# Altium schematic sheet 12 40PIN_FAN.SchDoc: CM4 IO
size 297 x 209 mm; Page Create Date: March  8, 1995; Page Number: 12; Page Size: A4; Comment: radxa_1010; Page Count: 19; RevCode: V1.10; Doc: 12 40PIN/FAN; DsnPath: D:\WMS\黄工\[RC126]CM4_IO_V1.10\[RC126]_V1.10\CM4 IO_V1.10.DSN; SchematicName: CM4 IO V1.10; PageName: 12 40PIN/FAN; PageSize: A4; TopSchematic: True
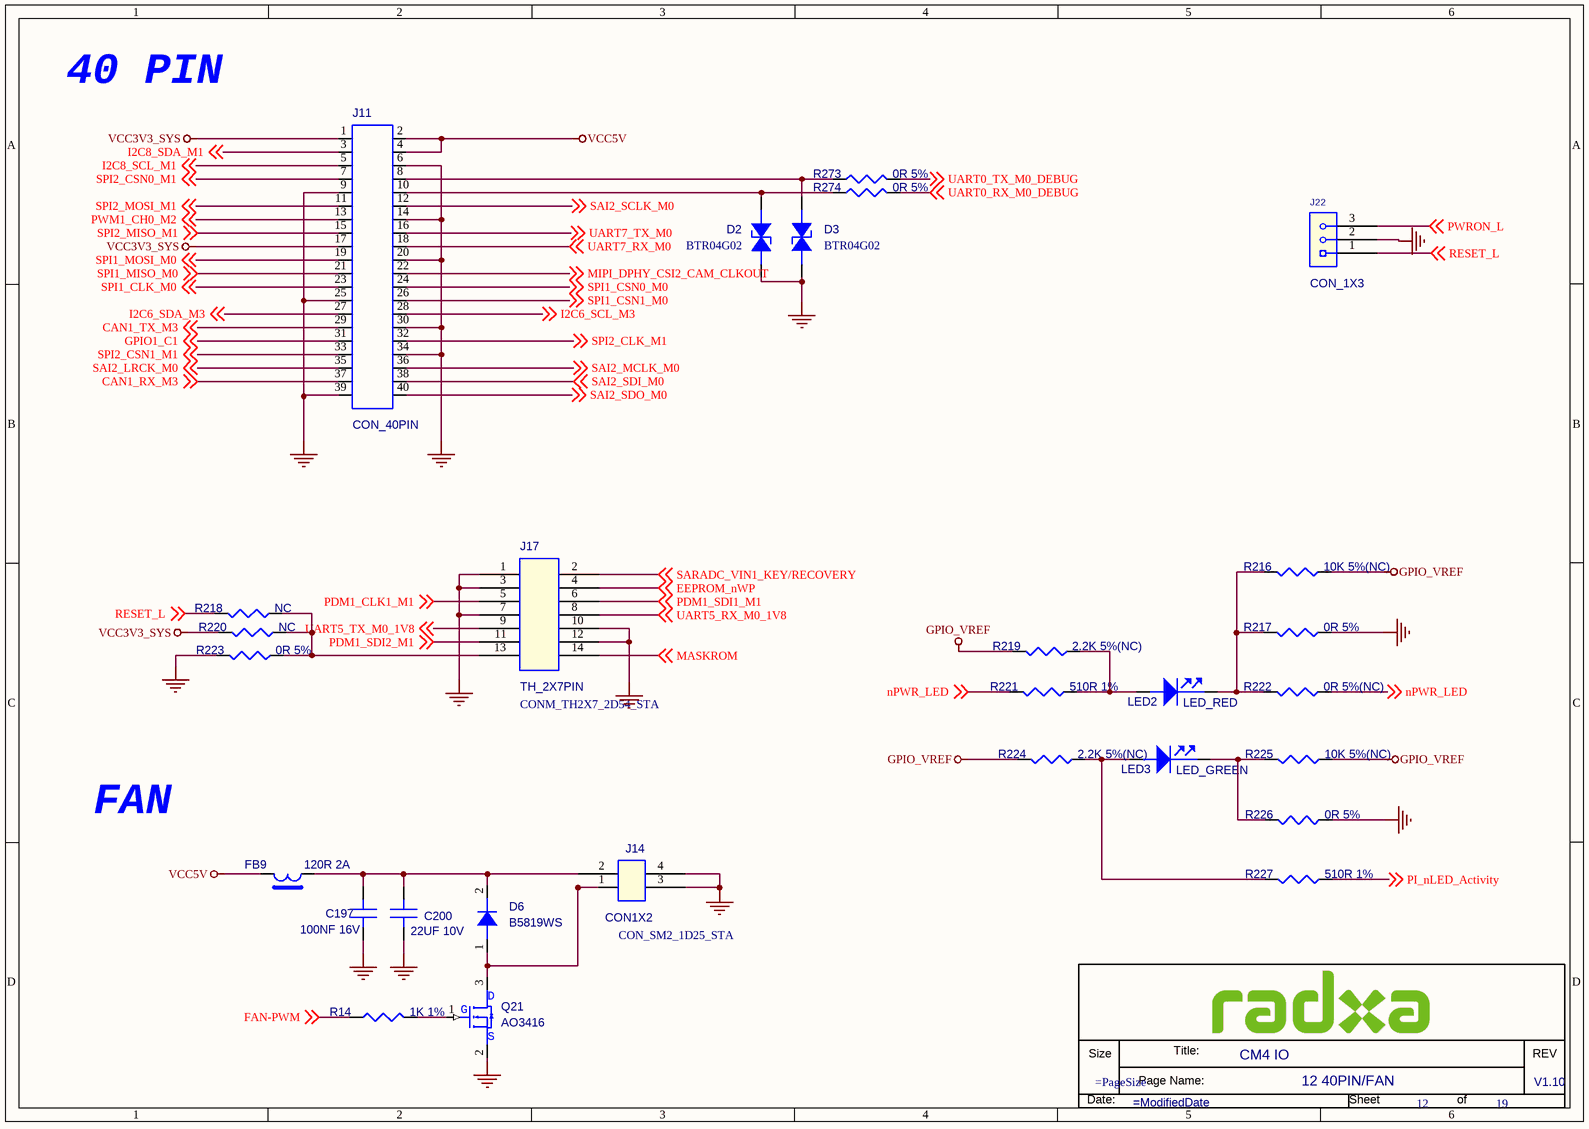
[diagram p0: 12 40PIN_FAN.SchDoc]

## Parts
*  Doc: 12 40PIN/FAN  RevCode: V1.10  Title: CM4 IO  Page Number: 12  Page Count: 19  (hidden comment: radxa_1010)  (graphical)
C197  100NF 16V  [C0201]
C200  22UF 10V  [C0603]
D2  BTR04G02  [DFN1006-2L]
D3  BTR04G02  [DFN1006-2L]
D6  B5819WS  [SOD_323]
FB9  120R 2A  [FB0402]
J11  CON_40PIN  [CON_TH20X2_2D54_STA]
J14  CON1X2  [CON_SM2_1D25_STA]
J17  TH_2X7PIN  [CONM_TH2X7_2D54_STA]
J22  CON_1X3  [CON_TH1X3_2D54_STA]
LED2  LED_RED  [LED_D0603]
LED3  LED_GREEN  [LED_D0603]
Q21  AO3416  [SOT_23]
R14  1K 1%  [R0402]
R216  10K 5%(NC)  [R0402]
R217  0R 5%  [R0402]
R218  NC  [R0402]
R219  2.2K 5%(NC)  [R0402]
R220  NC  [R0402]
R221  510R 1%  [R0402]
R222  0R 5%(NC)  [R0402]
R223  0R 5%  [R0402]
R224  2.2K 5%(NC)  [R0402]
R225  10K 5%(NC)  [R0402]
R226  0R 5%  [R0402]
R227  510R 1%  [R0402]
R273  0R 5%  [R0402]
R274  0R 5%  [R0402]

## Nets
GND: C197.2(B) C200.2(B) D2.2(CATHODE) D3.2(CATHODE) J11.6 J11.9 J11.14 J11.20 J11.25 J11.30 J11.34 J11.39 J14.3 J14.4 J17.1 J17.3 J17.7 J17.10 J17.12 J22.2 Q21.2(S) R217.2 R223.2 R226.2
GPIO_VREF: R216.2 R219.1 R224.1 R225.2
VCC3V3_SYS: J11.1 J11.17 R220.2
VCC5V: FB9.1 J11.2 J11.4
CAN1_RX_M3: J11.37 ; off-sheet CAN1_RX_M3
CAN1_TX_M3: J11.29 ; off-sheet CAN1_TX_M3
EEPROM_nWP: J17.4 ; off-sheet EEPROM_nWP
FAN-PWM: R14.1 ; off-sheet FAN-PWM
GPIO1_C1: J11.31 ; off-sheet GPIO1_C1
I2C6_SCL_M3: J11.28 ; off-sheet I2C6_SCL_M3
I2C6_SDA_M3: J11.27 ; off-sheet I2C6_SDA_M3
I2C8_SCL_M1: J11.5 ; off-sheet I2C8_SCL_M1
I2C8_SDA_M1: J11.3 ; off-sheet I2C8_SDA_M1
MASKROM: J17.14 ; off-sheet MASKROM
MIPI_DPHY_CSI2_CAM_CLKOUT: J11.22 ; off-sheet MIPI_DPHY_CSI2_CAM_CLKOUT
nPWR_LED: R221.1 R222.2 ; off-sheet nPWR_LED
PDM1_CLK1_M1: J17.5 ; off-sheet PDM1_CLK1_M1
PDM1_SDI1_M1: J17.6 ; off-sheet PDM1_SDI1_M1
PDM1_SDI2_M1: J17.11 ; off-sheet PDM1_SDI2_M1
PI_nLED_Activity: R227.2 ; off-sheet PI_nLED_Activity
PWM1_CH0_M2: J11.13 ; off-sheet PWM1_CH0_M2
PWRON_L: J22.3 ; off-sheet PWRON_L
RESET_L: J22.1 R218.2 ; off-sheet RESET_L
SAI2_LRCK_M0: J11.35 ; off-sheet SAI2_LRCK_M0
SAI2_MCLK_M0: J11.36 ; off-sheet SAI2_MCLK_M0
SAI2_SCLK_M0: J11.12 ; off-sheet SAI2_SCLK_M0
SAI2_SDI_M0: J11.38 ; off-sheet SAI2_SDI_M0
SAI2_SDO_M0: J11.40 ; off-sheet SAI2_SDO_M0
SARADC_VIN1_KEY/RECOVERY: J17.2 ; off-sheet SARADC_VIN1_KEY/RECOVERY
SPI1_CLK_M0: J11.23 ; off-sheet SPI1_CLK_M0
SPI1_CSN0_M0: J11.24 ; off-sheet SPI1_CSN0_M0
SPI1_CSN1_M0: J11.26 ; off-sheet SPI1_CSN1_M0
SPI1_MISO_M0: J11.21 ; off-sheet SPI1_MISO_M0
SPI1_MOSI_M0: J11.19 ; off-sheet SPI1_MOSI_M0
SPI2_CLK_M1: J11.32 ; off-sheet SPI2_CLK_M1
SPI2_CSN0_M1: J11.7 ; off-sheet SPI2_CSN0_M1
SPI2_CSN1_M1: J11.33 ; off-sheet SPI2_CSN1_M1
SPI2_MISO_M1: J11.15 ; off-sheet SPI2_MISO_M1
SPI2_MOSI_M1: J11.11 ; off-sheet SPI2_MOSI_M1
UART0_RX_M0_DEBUG: R274.2 ; off-sheet UART0_RX_M0_DEBUG
UART0_TX_M0_DEBUG: R273.2 ; off-sheet UART0_TX_M0_DEBUG
UART5_RX_M0_1V8: J17.8 ; off-sheet UART5_RX_M0_1V8
UART5_TX_M0_1V8: J17.9 ; off-sheet UART5_TX_M0_1V8
UART7_RX_M0: J11.18 ; off-sheet UART7_RX_M0
UART7_TX_M0: J11.16 ; off-sheet UART7_TX_M0
NetC197_1: C197.1(A) C200.1(A) D6.2(K) FB9.2 J14.2
NetD2_1: D2.1(ANODE) J11.10 R274.1
NetD3_1: D3.1(ANODE) J11.8 R273.1
NetD6_1: D6.1(A) J14.1 Q21.3(D)
NetJ17_13: J17.13 R218.1 R220.1 R223.1
NetLED2_1: LED2.1(ANODE) R219.2 R221.2
NetLED2_2: LED2.2(CATHODE) R216.1 R217.1 R222.1
NetLED3_1: LED3.1(ANODE) R224.2 R227.1
NetLED3_2: LED3.2(CATHODE) R225.1 R226.1
NetQ21_1: Q21.1(G) R14.2

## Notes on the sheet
- 40 PIN
- FAN

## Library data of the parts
C197 = C: SMD  0201  100NF  16V  X5R  ±20%  ROHS; PARTS: 1; Part Reference: C197; Part Number: A1C01.00099; OriginalSymbolOrigin: (0,30); PKG_TYPE: CAP2-100-250; LEVEL: STD; PINSWAP: (A,B)
C200 = C: SMD  0603  22UF  10V  X5R  ±20%  ROHS; PARTS: 1; Part Reference: C200; Part Number: A1C01.00015; OriginalSymbolOrigin: (0,30); PKG_TYPE: CAP2-100-250; LEVEL: STD; PINSWAP: (A,B)
D2 = ESD: SMD  编带  0402  BTR04G02  B-tron  ROHS; Part Reference: D2; Part Number: A1D02.00002; Parameter: ESD-台舟 ESD5341N-封装 esd0402; ID: DE-E0004; Preferred: 6715f349cd0bc5; Temp Coeff: -50℃ to +125℃; PCB Footprint: ESD_D0402
D3 = ESD: SMD  编带  0402  BTR04G02  B-tron  ROHS; Part Reference: D3; Part Number: A1D02.00002; Parameter: ESD-台舟 ESD5341N-封装 esd0402; ID: DE-E0004; Temp Coeff: -50℃ to +125℃; Preferred: 6715f349cd0bc5; PCB Footprint: ESD_D0402
D6 = DIODE_Dup1: SMD  编带  SOD-323  B5819WS  CJ  ROHS; Part Reference: D6; Manufacturer: 长电; Part Number: A1D02.00005; RK PN: B5819W; Priority: A; Temp Coeff: -55℃ ~ ＋150℃
FB9 = BEAD: SMD  0402  FB120R  2A  ±25%  ROHS; Part Reference: FB9; Part Number: A1L09.00004; Preferred: 6715f349cd0bc5; Temp Coeff: -55℃ to +125℃
J11 = CON_TH2X20: DIP  排针座  2*20PIN  180度  2.54mm脚距  中间朔高2.5mm  针长一端6.1mm  另一端3.0mm  彩色  PH2.54  2*20P  彩印 L=11.6/3.0  国意英  ROHS; Part Reference: J11; Part Number: A1J01.00012; OriginalSymbolOrigin: (-100,550); Preferred: 6715f349cd0bc5; Temp Coeff: -40℃ to +105℃
J14 = CON_1X2: SMD  母座  1*2PIN  90度  立贴  1.25mm脚距  9T  X9821WVS-02-9TSN  白色  星坤  ROHS; Part Reference: J14; Part Number: A1J01.00089; Temp Coeff: -25℃ to +85℃; Preferred: 6715f352cd0bcd
J17 = TH_2X7PIN: DIP  排针座  2*7PIN  180度  2.54mm脚距  中间朔高2.5mm  针长一端6.1mm  另一端3.0mm  黑色  PH2.54 2*7P L=11.6/3.0 S/T  国意英  ROHS; Part Reference: J17; Part Number: A1J02.00017; Preferred: 6715f349cd0bc5
J22 = CON_1X3: DIP  排针座  1*3PIN  180度  2.54mm脚距  中间朔高2.5mm  针长一端6.1mm  另一端3.0mm  材质LCP  黑色  PH2.54 1*3P L=11.6/3.0  国意英  ROHS; Part Reference: J22; Part Number: A1J02.00013; OriginalSymbolOrigin: (-50,50); Temp Coeff: -40°C to +85°C; Preferred: 6715f349cd0bc5
LED2 = LED: SMD  编带  0603  发红光  单色  mcd=150  IF=20mA  无色散光  EY-PB0603RC-010F  恩域光电  ROHS; Part Reference: LED2; Part Number: A1D03.00003; RK PN: LED_GREEN; Priority: A; Temp Coeff: -40℃ to +85℃; Preferred: 6715f349cd0bc5
LED3 = LED: SMD  编带  0603  发绿光  单色  mcd=150  IF=20mA  无色散光  EY-TB0603GC-010F  恩域光电  ROHS; Part Reference: LED3; Part Number: A1D03.00002; Priority: A; Temp Coeff: -40℃ to +85℃
Q21 = MOSFET_NPN: SMD  编带  SOT-23-3L  AO3416  N沟道  AOS  ROHS; Part Reference: Q21; Part Number: A1D01.00010; Temp Coeff: -55℃ to ＋150℃
R14 = R: SMD  0201  1K  1/20W  ±1%  ROHS; Part Reference: R14; Part Number: A1R01.00111; PCB Footprint: R0201; Preferred: 6715f349cd0bc5
R216 = R: SMD  0201  10K  1/20W  ±5%  ROHS; Part Reference: R216; Part Number: A1R01.00012; PCB Footprint: R0201; Temp Coeff: -55℃ to +125℃; Preferred: 6715f349cd0bc5
R217 = R: SMD  0201  0R  1/20W  ±5%  ROHS; Part Reference: R217; Part Number: A1R01.00027; PCB Footprint: R0201; Preferred: 6715f349cd0bc5; Temp Coeff: -55℃ to +125℃
R218 = R: SMD  0201  0R  1/20W  ±5%  ROHS; Part Reference: R218; Part Number: A1R01.00027; PCB Footprint: R0201; Preferred: 6715f349cd0bc5; Temp Coeff: -55℃ to +125℃
R219 = R: SMD  0201  2.2K  1/20W  ±5%  ROHS; Part Reference: R219; Part Number: A1R01.00016; PCB Footprint: R0201; Preferred: 6715f349cd0bc5; Temp Coeff: -55℃ to +125℃
R220 = R: SMD  0201  10K  1/20W  ±5%  ROHS; Part Reference: R220; Part Number: A1R01.00012; PCB Footprint: R0201; Preferred: 6715f349cd0bc5; Temp Coeff: -55℃ to +125℃
R221 = R: SMD  0201  2.2K  1/20W  ±5%  ROHS; Part Reference: R221; Part Number: A1R01.00016; PCB Footprint: R0201; Preferred: 6715f349cd0bc5; Temp Coeff: -55℃ to +125℃
R222 = R: SMD  0201  0R  1/20W  ±5%  ROHS; Part Reference: R222; Part Number: A1R01.00027; PCB Footprint: R0201; Temp Coeff: -55℃ to +125℃; Preferred: 6715f349cd0bc5
R223 = R: SMD  0201  0R  1/20W  ±5%  ROHS; Part Reference: R223; Part Number: A1R01.00027; PCB Footprint: R0201; Temp Coeff: -55℃ to +125℃; Preferred: 6715f349cd0bc5
R224 = R: SMD  0201  2.2K  1/20W  ±5%  ROHS; Part Reference: R224; Part Number: A1R01.00016; PCB Footprint: R0201; Temp Coeff: -55℃ to +125℃; Preferred: 6715f349cd0bc5
R225 = R: SMD  0201  10K  1/20W  ±5%  ROHS; Part Reference: R225; Part Number: A1R01.00012; PCB Footprint: R0201; Temp Coeff: -55℃ to +125℃; Preferred: 6715f349cd0bc5
R226 = R: SMD  0201  0R  1/20W  ±5%  ROHS; Part Reference: R226; Part Number: A1R01.00027; PCB Footprint: R0201; Preferred: 6715f349cd0bc5; Temp Coeff: -55℃ to +125℃
R227 = R: SMD  0201  0R  1/20W  ±5%  ROHS; Part Reference: R227; Part Number: A1R01.00027; PCB Footprint: R0201; Preferred: 6715f349cd0bc5; Temp Coeff: -55℃ to +125℃
R273 = R: SMD  0201  0R  1/20W  ±5%  ROHS; Part Reference: R273; Part Number: A1R01.00027; PCB Footprint: R0201; Temp Coeff: -55℃ to +125℃; Preferred: 6715f349cd0bc5
R274 = R: SMD  0201  0R  1/20W  ±5%  ROHS; Part Reference: R274; Part Number: A1R01.00027; PCB Footprint: R0201; Temp Coeff: -55℃ to +125℃; Preferred: 6715f349cd0bc5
